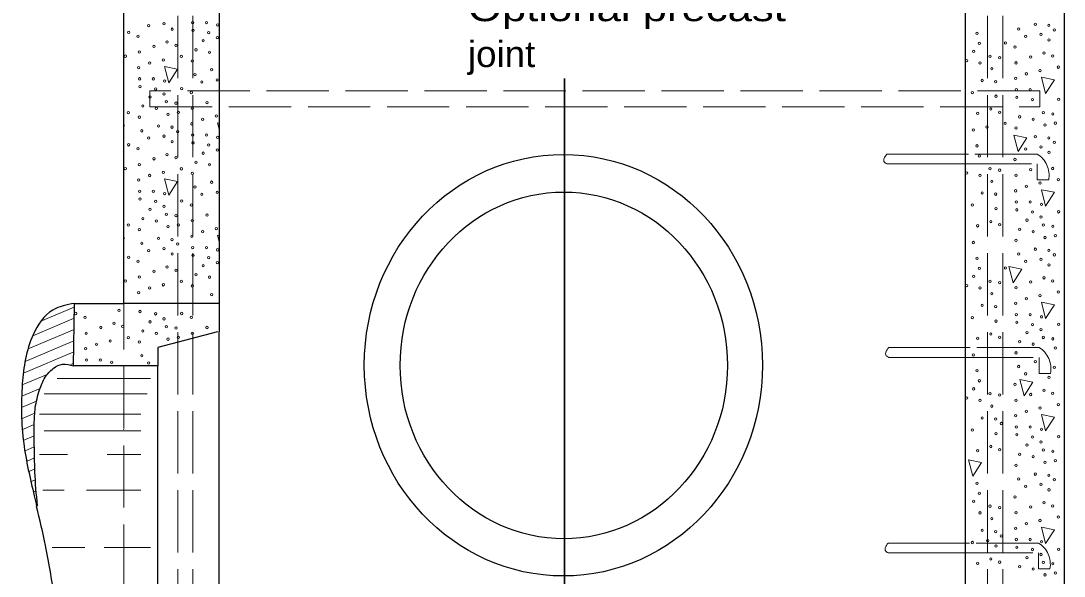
# Model space of a CAD drawing. Extents: x 1329.9 to 1363.9, y 715.5 to 737.5.
# Drawn here: x 1339.9 to 1346.13, y 722.08 to 725.4 of the extents above; entities that cross this region are included whole.
import ezdxf

# ---------------------------------------------------------------- set-up
doc = ezdxf.new("R2010")
doc.units = 0
doc.header["$LTSCALE"] = 0.062
doc.linetypes.add('LONG_DASHED', pattern=[7.5, 6, -1.5])
doc.layers.add('1', color=7, linetype='Continuous', lineweight=13)

msp = doc.modelspace()

# ---------------------------------------------------------------- linework, layer by layer
at = {"layer": '1', "lineweight": 25}
for p, q in [((1345.54217, 721.19308), (1345.54217, 728.652)), ((1341.08508, 728.63108), (1341.08508, 723.71042)), ((1340.21483, 723.33767), (1340.21925, 723.71042)), ((1341.08508, 723.71042), (1340.5145, 723.71042)), ((1341.08508, 723.71042), (1341.08508, 723.53967)), ((1341.08508, 720.95883), (1341.08508, 723.53967)), ((1340.71817, 718.95617), (1340.71817, 723.33767))]:
    msp.add_line(p, q, dxfattribs=at)
at = {"layer": '1', "linetype": 'LONG_DASHED'}
for p, q in [((1345.76417, 718.91875), (1345.76417, 728.66458)), ((1340.83683, 718.91875), (1340.83683, 728.63117)), ((1340.92608, 718.91875), (1340.92608, 728.63467)), ((1345.67267, 718.91875), (1345.67267, 728.64083)), ((1345.97058, 724.60183), (1345.55908, 724.60183)), ((1340.5145, 718.71467), (1340.5145, 723.72467)), ((1345.98133, 723.44683), (1345.56983, 723.44683)), ((1345.978, 722.27875), (1345.5665, 722.27875))]:
    msp.add_line(p, q, dxfattribs=at)
at = {"layer": '1', "lineweight": 35}
msp.add_line((1343.146, 725.05433), (1343.146, 717.76983), dxfattribs=at)
at = {"layer": '1'}
for p, q in [((1341.075, 724.78933), (1341.08508, 724.75125)), ((1341.08508, 724.78742), (1341.075, 724.78933)), ((1345.55908, 724.60183), (1345.07308, 724.60183)), ((1345.07308, 724.54325), (1345.56392, 724.54325)), ((1341.075, 724.11767), (1341.08508, 724.07958)), ((1341.08508, 724.11575), (1341.075, 724.11767)), ((1340.01917, 723.60375), (1340.219, 723.68842)), ((1340.21483, 723.33767), (1340.21925, 723.71042)), ((1340.21483, 723.33767), (1340.21925, 723.71042)), ((1339.97025, 723.51625), (1340.21817, 723.62133)), ((1339.94308, 723.43808), (1340.21742, 723.55433)), ((1339.9255, 723.36408), (1340.21658, 723.48742)), ((1339.91508, 723.29292), (1340.21583, 723.42033)), ((1345.56983, 723.44683), (1345.08383, 723.44683)), ((1340.19725, 723.34567), (1340.215, 723.35325)), ((1345.08383, 723.38825), (1345.57467, 723.38825)), ((1340.51242, 723.33767), (1340.5145, 723.34017)), ((1339.90817, 723.22333), (1340.05725, 723.2865)), ((1340.11575, 723.2615), (1340.67325, 723.2615)), ((1339.90583, 723.15558), (1340.01408, 723.2015)), ((1340.03958, 723.17067), (1340.65417, 723.17067)), ((1339.90342, 723.08792), (1339.99325, 723.126)), ((1339.90325, 723.02108), (1339.983, 723.05492)), ((1340.01092, 723.04967), (1340.61608, 723.04967)), ((1339.90625, 722.95567), (1339.97933, 722.98667)), ((1339.91425, 722.89242), (1339.97867, 722.91975)), ((1340.03958, 722.94875), (1340.61608, 722.94875)), ((1340.51242, 722.956), (1340.5145, 722.95833)), ((1339.925, 722.83025), (1339.98008, 722.85358)), ((1340.01092, 722.8075), (1340.17775, 722.8075)), ((1340.416, 722.8075), (1340.61608, 722.8075)), ((1339.93675, 722.76858), (1339.98167, 722.78758)), ((1339.94875, 722.70692), (1339.98325, 722.72167)), ((1339.96158, 722.64575), (1339.98625, 722.65617)), ((1339.97442, 722.5845), (1339.98967, 722.59092)), ((1340.03, 722.59575), (1340.15875, 722.59575)), ((1340.29208, 722.59575), (1340.61608, 722.59575)), ((1339.988, 722.5235), (1339.994, 722.52608)), ((1340.08717, 722.25275), (1340.2825, 722.25275)), ((1340.39692, 722.25275), (1340.67325, 722.25275)), ((1345.5665, 722.27875), (1345.08058, 722.27875)), ((1345.08058, 722.22017), (1345.57142, 722.22017))]:
    msp.add_line(p, q, dxfattribs=at)
at = {"layer": '1', "lineweight": 25}
for points in [[(1346.13117, 728.65933), (1346.13117, 718.46475), (1340.5145, 718.46475), (1340.5145, 718.71467)], [(1340.21925, 723.71042), (1340.5145, 723.71042), (1340.5145, 728.61575)], [(1341.075, 723.53967), (1340.71817, 723.44733), (1340.71817, 723.33767), (1340.21483, 723.33767)]]:
    msp.add_lwpolyline(points, dxfattribs=at)
at = {"layer": '1'}
for points in [[(1340.75783, 725.12517), (1340.78342, 725.02783), (1340.83575, 725.11)], [(1345.99517, 725.06092), (1346.02083, 724.9635), (1346.073, 725.04567)], [(1345.83067, 724.71517), (1345.85633, 724.61783), (1345.90858, 724.7)], [(1340.75783, 724.45358), (1340.78342, 724.35617), (1340.83575, 724.43833)], [(1345.99517, 724.38917), (1346.02083, 724.29192), (1346.073, 724.37408)], [(1345.80108, 723.93), (1345.82675, 723.83267), (1345.879, 723.91483)], [(1345.99517, 723.71758), (1346.02083, 723.62017), (1346.073, 723.70233)], [(1345.86683, 723.255), (1345.8925, 723.15775), (1345.94475, 723.23992)], [(1345.99517, 723.04592), (1346.02083, 722.94858), (1346.073, 723.03075)], [(1345.55967, 722.77592), (1345.58525, 722.67858), (1345.63758, 722.76067)], [(1345.99517, 722.37425), (1346.02083, 722.277), (1346.073, 722.35908)]]:
    msp.add_lwpolyline(points, close=True, dxfattribs=at)
at = {"layer": '1', "linetype": 'LONG_DASHED'}
msp.add_lwpolyline([(1345.98667, 724.97958), (1340.67083, 724.97958), (1340.67083, 724.88458), (1345.98667, 724.88458)], close=True, dxfattribs=at)
at = {"layer": '1'}
for points in [[(1340.5145, 724.76792), (1340.5185, 724.77417), (1340.5145, 724.775)], [(1340.5145, 724.09633), (1340.5185, 724.1025), (1340.5145, 724.10333)]]:
    msp.add_lwpolyline(points, dxfattribs=at)
at = {"layer": '1', "linetype": 'LONG_DASHED'}
for points in [[(1345.56392, 724.54325), (1345.97058, 724.54325), (1345.97058, 724.4475), (1346.03892, 724.4475)], [(1345.57467, 723.38825), (1345.98133, 723.38825), (1345.98133, 723.29258), (1346.04967, 723.29258)], [(1345.57142, 722.22017), (1345.978, 722.22017), (1345.978, 722.1245), (1346.04633, 722.1245)]]:
    msp.add_lwpolyline(points, dxfattribs=at)
at = {"layer": '1'}
for centre in [(1340.66341, 725.36902), (1340.75502, 725.38083), (1340.80329, 725.34787), (1340.92605, 725.38716), (1340.92858, 725.34093), (1341.00831, 725.38716), (1341.07592, 725.37356), (1345.85959, 725.34827), (1345.95892, 725.37732), (1346.03975, 725.37032), (1346.07343, 725.34374), (1340.54345, 725.32912), (1340.59997, 725.30555), (1340.98854, 725.27925), (1341.022, 725.32733), (1341.07249, 725.29738), (1345.61122, 725.32286), (1345.90072, 725.30472), (1345.99233, 725.31653), (1346.0406, 725.28357), (1340.69449, 725.24544), (1340.77332, 725.2708), (1340.82555, 725.25177), (1340.94545, 725.22456), (1345.62491, 725.26303), (1345.78076, 725.26482), (1345.83728, 725.24125), (1340.52373, 725.18678), (1340.60684, 725.21119), (1340.75016, 725.16468), (1340.85891, 725.18555), (1340.92404, 725.15835), (1341.02623, 725.21035), (1345.54836, 725.16026), (1345.59145, 725.21495), (1345.68914, 725.18595), (1345.7465, 725.17773), (1345.9318, 725.18114), (1346.01063, 725.2065), (1346.06286, 725.18747), (1340.60372, 725.11844), (1340.66875, 725.14565), (1341.03881, 725.10579), (1345.62914, 725.14605), (1345.69935, 725.11157), (1345.84415, 725.14689), (1345.98747, 725.10038), (1346.09622, 725.12125), (1340.60885, 725.05134), (1340.69111, 725.05134), (1340.75872, 725.03773), (1340.93948, 725.07675), (1340.98061, 725.0332), (1341.07222, 725.04501), (1345.64172, 725.0415), (1345.72256, 725.0345), (1345.84103, 725.05414), (1345.90605, 725.08135), (1340.61139, 725.0051), (1340.7048, 724.9915), (1340.86065, 724.99329), (1340.91717, 724.96973), (1345.58352, 724.9689), (1345.84616, 724.98704), (1345.92842, 724.98704), (1340.67134, 724.94342), (1340.75529, 724.96156), (1340.76903, 724.91443), (1340.82639, 724.9062), (1341.01169, 724.90962), (1345.7234, 724.94774), (1345.84869, 724.9408), (1345.94211, 724.9272), (1346.09796, 724.92899), (1340.54171, 724.84973), (1340.62825, 724.88874), (1340.70903, 724.87453), (1340.84093, 724.85096), (1340.92404, 724.87536), (1345.6146, 724.84532), (1345.69343, 724.87067), (1345.74566, 724.85164), (1346.00634, 724.85013), (1346.0637, 724.8419), (1340.60684, 724.82253), (1340.77924, 724.84005), (1340.92092, 724.78262), (1340.98594, 724.80982), (1341.06736, 724.82885), (1345.77902, 724.78543), (1345.86556, 724.82444), (1345.94634, 724.81023), (1346.07824, 724.78666), (1340.62228, 724.74092), (1340.72161, 724.76997), (1340.80244, 724.76298), (1340.83612, 724.73639), (1345.58886, 724.74552), (1345.67027, 724.76455), (1345.84415, 724.75823), (1346.01655, 724.77575), (1340.54345, 724.65747), (1340.66341, 724.69738), (1340.75502, 724.70919), (1340.80329, 724.67622), (1340.92605, 724.71551), (1340.92858, 724.66928), (1341.00831, 724.71551), (1341.022, 724.65568), (1341.07592, 724.70191), (1345.95892, 724.70567), (1346.03975, 724.69868), (1346.07343, 724.67209), (1340.59997, 724.63391), (1340.77332, 724.59915), (1340.98854, 724.6076), (1341.07249, 724.62574), (1345.61122, 724.65121), (1345.90072, 724.63308), (1345.99233, 724.64489), (1346.0406, 724.61192), (1340.60684, 724.53954), (1340.69449, 724.5738), (1340.82555, 724.58012), (1340.94545, 724.55292), (1341.02623, 724.5387), (1345.62491, 724.59138), (1345.83728, 724.56961), (1340.52373, 724.51514), (1340.66875, 724.474), (1340.75016, 724.49303), (1340.85891, 724.51391), (1340.92404, 724.48671), (1345.54836, 724.48862), (1345.62914, 724.4744), (1345.68914, 724.51431), (1345.7465, 724.50608), (1345.84415, 724.47524), (1345.9318, 724.5095), (1346.06286, 724.51582), (1340.60372, 724.4468), (1341.03881, 724.43415), (1345.69935, 724.43992), (1345.90605, 724.4097), (1345.98747, 724.42873), (1346.09622, 724.44961), (1340.60885, 724.37969), (1340.69111, 724.37969), (1340.75872, 724.36609), (1340.93948, 724.4051), (1340.98061, 724.36156), (1341.07222, 724.37337), (1345.64172, 724.36985), (1345.72256, 724.36285), (1345.84103, 724.3825), (1340.61139, 724.33346), (1340.7048, 724.31986), (1340.75529, 724.28991), (1340.86065, 724.32165), (1340.91717, 724.29809), (1345.58352, 724.29726), (1345.84616, 724.31539), (1345.92842, 724.31539), (1345.99603, 724.30179), (1340.67134, 724.27178), (1340.76903, 724.24279), (1340.82639, 724.23456), (1341.01169, 724.23797), (1345.7234, 724.2761), (1345.84869, 724.26916), (1345.94211, 724.25556), (1345.9926, 724.22561), (1346.09796, 724.25735), (1340.54171, 724.17808), (1340.62825, 724.2171), (1340.70903, 724.20288), (1340.77924, 724.1684), (1340.84093, 724.17932), (1340.92404, 724.20372), (1341.06736, 724.15721), (1345.6146, 724.17367), (1345.69343, 724.19903), (1345.74566, 724.18), (1345.90865, 724.20748), (1346.00634, 724.17849), (1346.0637, 724.17026), (1340.60684, 724.15088), (1340.72161, 724.09833), (1340.92092, 724.11098), (1340.98594, 724.13818), (1345.86556, 724.1528), (1345.94634, 724.13858), (1346.01655, 724.1041), (1346.07824, 724.11502), (1340.62228, 724.06928), (1340.75502, 724.03754), (1340.80244, 724.09133), (1340.83612, 724.06474), (1340.92605, 724.04387), (1341.00831, 724.04387), (1345.58886, 724.07388), (1345.84415, 724.08658), (1345.95892, 724.03403), (1340.54345, 723.98583), (1340.66341, 724.02573), (1340.80329, 724.00458), (1340.92858, 723.99764), (1341.022, 723.98403), (1341.07592, 724.03027), (1345.61122, 723.97957), (1345.85959, 724.00498), (1345.99233, 723.97324), (1346.03975, 724.02703), (1346.07343, 724.00044), (1340.59997, 723.96226), (1340.77332, 723.9275), (1340.82555, 723.90847), (1340.98854, 723.93596), (1341.07249, 723.95409), (1345.62491, 723.91974), (1345.78076, 723.92153), (1345.90072, 723.96143), (1346.0406, 723.94028), (1340.60684, 723.8679), (1340.69449, 723.90215), (1340.94545, 723.88127), (1341.02623, 723.86706), (1345.59145, 723.87166), (1346.01063, 723.8632), (1340.52373, 723.84349), (1340.66875, 723.80235), (1340.75016, 723.82138), (1340.85891, 723.84226), (1340.92404, 723.81506), (1345.54836, 723.81697), (1345.62914, 723.80276), (1345.68914, 723.84266), (1345.7465, 723.83444), (1345.84415, 723.8036), (1345.9318, 723.83785), (1346.06286, 723.84417), (1340.60372, 723.77515), (1341.03881, 723.7625), (1345.69935, 723.76828), (1345.90605, 723.73805), (1345.98747, 723.75708), (1346.09622, 723.77796), (1340.48609, 723.66875), (1340.61139, 723.66181), (1345.64172, 723.6982), (1345.72256, 723.69121), (1345.84103, 723.71085), (1340.22625, 723.65), (1340.28277, 723.62644), (1340.67134, 723.60013), (1340.7048, 723.64821), (1340.75529, 723.61827), (1340.86065, 723.65), (1340.91717, 723.62644), (1345.58352, 723.62561), (1345.7234, 723.60445), (1345.84616, 723.64374), (1345.84869, 723.59751), (1345.92842, 723.64374), (1345.99603, 723.63014), (1340.37729, 723.56633), (1340.45612, 723.59168), (1340.50835, 723.57265), (1340.62825, 723.54545), (1340.76903, 723.57114), (1340.82639, 723.56291), (1341.01169, 723.56633), (1345.90865, 723.53583), (1345.94211, 723.58391), (1345.9926, 723.55397), (1346.09796, 723.5857), (1340.28964, 723.53207), (1340.43296, 723.48556), (1340.54171, 723.50644), (1340.60684, 723.47924), (1340.70903, 723.53123), (1340.77924, 723.49676), (1340.84093, 723.50767), (1340.92404, 723.53207), (1345.6146, 723.50203), (1345.69343, 723.52738), (1345.74566, 723.50835), (1345.86556, 723.48115), (1346.00634, 723.50684), (1346.0637, 723.49861), (1340.28652, 723.43933), (1340.35155, 723.46653), (1345.84415, 723.41494), (1345.94634, 723.46693), (1346.07824, 723.44337), (1340.29165, 723.37222), (1340.37391, 723.37222), (1340.44152, 723.35862), (1340.62228, 723.39763), (1340.66341, 723.35409), (1345.58886, 723.40223), (1345.95892, 723.36238), (1345.61122, 723.30792), (1345.85959, 723.33333), (1345.90072, 723.28979), (1346.07343, 723.3288), (1345.62491, 723.24809), (1345.83728, 723.22632), (1346.0406, 723.26863), (1345.59145, 723.20001), (1345.68914, 723.17102), (1345.7465, 723.16279), (1345.9318, 723.1662), (1346.01063, 723.19156), (1346.06286, 723.17253), (1345.54836, 723.14533), (1345.62914, 723.13111), (1345.69935, 723.09663), (1345.84415, 723.13195), (1346.09622, 723.10632), (1345.84103, 723.03921), (1345.90605, 723.06641), (1345.98747, 723.08544), (1345.64172, 723.02656), (1345.72256, 723.01956), (1345.75623, 722.99298), (1345.84616, 722.9721), (1345.92842, 722.9721), (1345.58352, 722.95396), (1345.7234, 722.93281), (1345.84869, 722.92587), (1345.94211, 722.91227), (1345.99603, 722.9585), (1346.09796, 722.91406), (1345.69343, 722.85574), (1345.90865, 722.86419), (1345.9926, 722.88232), (1345.6146, 722.83038), (1345.74566, 722.83671), (1345.86556, 722.8095), (1345.94634, 722.79529), (1346.00634, 722.8352), (1346.0637, 722.82697), (1345.84415, 722.74329), (1346.01655, 722.76081), (1346.07824, 722.77172), (1345.85959, 722.66169), (1345.95892, 722.69074), (1346.03975, 722.68374), (1345.61122, 722.63628), (1345.90072, 722.61814), (1345.99233, 722.62995), (1346.07343, 722.65715), (1345.62491, 722.57644), (1345.83728, 722.55467), (1346.0406, 722.59698), (1345.59145, 722.52837), (1345.68914, 722.49937), (1345.7465, 722.49114), (1345.9318, 722.49456), (1346.01063, 722.51991), (1346.06286, 722.50088), (1345.62914, 722.45947), (1345.69935, 722.42499), (1345.84415, 722.46031), (1345.98747, 722.41379), (1346.09622, 722.43467), (1345.64172, 722.35491), (1345.84103, 722.36756), (1345.90605, 722.39476), (1345.67513, 722.29413), (1345.72256, 722.34792), (1345.75623, 722.32133), (1345.84616, 722.30045), (1345.92842, 722.30045), (1345.99603, 722.28685), (1345.58352, 722.28232), (1345.7234, 722.26116), (1345.84869, 722.25422), (1345.94211, 722.24062), (1346.09796, 722.24241), (1345.69343, 722.18409), (1345.74566, 722.16506), (1345.90865, 722.19254), (1345.9926, 722.21068), (1346.00634, 722.16355), (1345.6146, 722.15874), (1345.86556, 722.13786), (1345.94634, 722.12364), (1346.0637, 722.15532), (1346.07824, 722.10008), (1346.01655, 722.08916)]:
    msp.add_ellipse(centre, major_axis=(0, 0.00718), ratio=0.944544, dxfattribs=at)
at = {"layer": '1', "lineweight": 25}
for centre, major_axis in [((1343.14003, 723.34143), (0, 1.25874)), ((1343.14291, 723.34028), (0, -1.03498))]:
    msp.add_ellipse(centre, major_axis=major_axis, ratio=0.944544, dxfattribs=at)
at = {"layer": '1', "linetype": 'LONG_DASHED'}
for centre in [(1345.90432, 724.4748), (1345.91509, 723.31987), (1345.9118, 722.15179)]:
    msp.add_ellipse(centre, major_axis=(0, -0.14504), ratio=0.944544, start_param=1.3817766, end_param=2.6372404, dxfattribs=at)
at = {"layer": '1'}
for points in [[(1345.07308, 724.60183), (1345.05517, 724.57275), (1345.05517, 724.55733), (1345.07308, 724.54325)], [(1345.08383, 723.44683), (1345.066, 723.41783), (1345.066, 723.40242), (1345.08383, 723.38825)], [(1345.08058, 722.27875), (1345.06267, 722.24975), (1345.06267, 722.23433), (1345.08058, 722.22017)]]:
    msp.add_spline(points, degree=3, dxfattribs=at)
at = {"layer": '1', "lineweight": 25}
for points in [[(1340.21925, 723.71042), (1340.08967, 723.6705), (1339.97242, 723.52225), (1339.90842, 723.23042), (1339.9165, 722.87458), (1339.97925, 722.56117), (1339.99383, 722.49733)], [(1339.99883, 722.50233), (1339.98367, 722.70483), (1339.98075, 722.82633), (1339.97867, 722.917), (1339.97942, 722.992), (1339.98583, 723.086), (1340.01158, 723.19492), (1340.04483, 723.269), (1340.09308, 723.322), (1340.14875, 723.34767), (1340.21483, 723.33767)], [(1340.02358, 719.1235), (1340.172, 719.25925), (1340.257, 719.52042), (1340.29025, 720.1055), (1340.27175, 720.58058), (1340.23458, 721.07567), (1340.17708, 721.54742), (1340.10675, 721.92825), (1340.04675, 722.26367), (1339.99383, 722.49733)]]:
    msp.add_spline(points, degree=3, dxfattribs=at)

# ---------------------------------------------------------------- texts
at = {"layer": '1'}
for s, width, p in [('Optional precast', 1.25, (1342.57017, 725.39583)), ('joint', 1.05, (1342.57017, 725.12175))]:
    msp.add_text(s, height=0.156, dxfattribs=dict(at, width=width)).set_placement(p)

doc.saveas('drawing.dxf')
